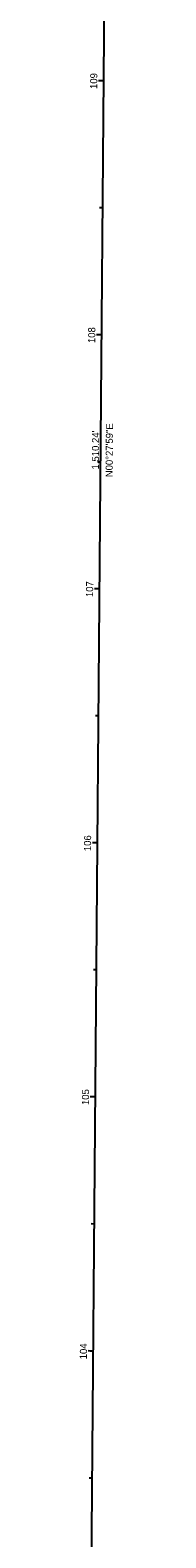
# Model space of a CAD drawing. Extents: x 217610 to 217676, y 457884 to 460293.
# Drawn here: x 217661 to 217675, y 459106 to 459699 of the extents above; entities that cross this region are included whole.
import ezdxf

# ---------------------------------------------------------------- set-up
doc = ezdxf.new("R2010")
doc.units = 0
for name, color, linetype in [('RW_X_CL', 7, 'Continuous'), ('RW_X_CL_100_Bearings', 7, 'Continuous'), ('RW_X_CL_100_Distances', 7, 'Continuous'), ('RW_X_CL_100_Stations', 7, 'Continuous'), ('RW_X_CL_500_Bearings', 7, 'Continuous'), ('RW_X_CL_500_Distances', 7, 'Continuous'), ('RW_X_CL_500_Stations', 7, 'Continuous')]:
    doc.layers.add(name, color=color, linetype=linetype)

msp = doc.modelspace()

# ---------------------------------------------------------------- linework, layer by layer
at = {"layer": 'RW_X_CL'}
msp.add_line((217663.13, 458779.17), (217675.43, 460289.35), dxfattribs=at)
at = {"layer": 'RW_X_CL_100_Stations'}
for p, q in [((217670.46, 459679.14), (217668.46, 459679.15)), ((217670.05, 459629.14), (217668.85, 459629.15)), ((217669.64, 459579.14), (217667.65, 459579.16)), ((217669.24, 459529.14), (217668.04, 459529.15)), ((217668.83, 459479.14), (217666.83, 459479.16)), ((217668.42, 459429.14), (217667.22, 459429.15)), ((217668.02, 459379.15), (217666.02, 459379.16)), ((217667.61, 459329.15), (217666.41, 459329.16)), ((217667.2, 459279.15), (217665.2, 459279.17)), ((217666.8, 459229.15), (217665.6, 459229.16)), ((217666.39, 459179.15), (217664.39, 459179.17)), ((217665.98, 459129.15), (217664.78, 459129.16))]:
    msp.add_line(p, q, dxfattribs=at)
at = {"layer": 'RW_X_CL_500_Stations'}
for p, q in [((217670.46, 459679.14), (217669.26, 459679.15)), ((217669.64, 459579.14), (217668.44, 459579.15)), ((217668.83, 459479.14), (217667.63, 459479.15)), ((217668.02, 459379.15), (217666.82, 459379.16)), ((217667.2, 459279.15), (217665.2, 459279.17)), ((217666.39, 459179.15), (217665.19, 459179.16))]:
    msp.add_line(p, q, dxfattribs=at)

# ---------------------------------------------------------------- texts
at = {"layer": 'RW_X_CL_100_Bearings'}
msp.add_text('N00°27\'59"E', height=2.8, rotation=89.53369, dxfattribs=at).set_placement((217673.99, 459523.1))
at = {"layer": 'RW_X_CL_100_Distances'}
msp.add_text("1,510.24'", height=2.8, rotation=89.53369, dxfattribs=at).set_placement((217668.59, 459526.17))
at = {"layer": 'RW_X_CL_100_Stations'}
for s, p in [('109', (217667.93, 459675.93)), ('108', (217667.12, 459575.91)), ('107', (217666.3, 459475.92)), ('106', (217665.49, 459375.91)), ('105', (217664.68, 459275.96)), ('104', (217663.86, 459175.89))]:
    msp.add_text(s, height=2.8, rotation=89.53369, dxfattribs=at).set_placement(p)
at = {"layer": 'RW_X_CL_500_Bearings'}
msp.add_text('N00°27\'59"E', height=2.8, rotation=89.53369, dxfattribs=at).set_placement((217673.99, 459523.1))
at = {"layer": 'RW_X_CL_500_Distances'}
msp.add_text("1,510.24'", height=2.8, rotation=89.53369, dxfattribs=at).set_placement((217668.59, 459526.17))
at = {"layer": 'RW_X_CL_500_Stations'}
msp.add_text('105', height=2.8, rotation=89.53369, dxfattribs=at).set_placement((217664.68, 459275.96))

doc.saveas('drawing.dxf')
